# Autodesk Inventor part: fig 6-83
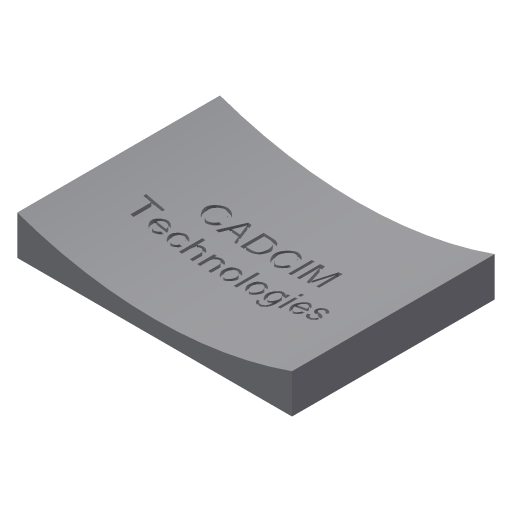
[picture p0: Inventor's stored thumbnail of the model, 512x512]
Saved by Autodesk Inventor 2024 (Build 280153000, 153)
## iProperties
Shininess: 64.0
Length Units: 11269
Angle Units: 11279
Time Units: 11290
Mass Units: 11283
Length Display Precision: 3
Angle Display Precision: 2
Compacted: True
Part Number: fig 6-83
Document SubType Name: Modeling
Created: 2002-12
Designer: deepak
Density: 1 g/cm^3
Material: Generic
Appearance: Default
Density: 0.0
Volumn: 0.0
Area: 0.0
PropertySet Name: Model Information
Control State: 0
Master: False
Checked Out: False
Author: deepak
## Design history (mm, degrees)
sketch "Sketch1"
  geometry: L1 (-39.922, 33.786)-(30.103, 33.786); L2 (30.103, 33.786)-(30.103, -17.894); L3 (30.103, -17.894)-(-39.922, -17.894); L4 (-39.922, -17.894)-(-39.922, 33.786)
  constraints: 8 end point, 2 parallel, 1 horizontal, 1 perpendicular
extrude "Extrusion1" new body sketch "Sketch1" distance "d0" = 10; taper "d1" = 0 deg
workplane "Work Plane1"
sketch "Sketch2"
  geometry: L1 (-37.656, 15.034)-(26.28, 15.034); L2 (26.28, 15.034)-(26.28, 10.168); L3 (26.28, 10.168)-(-37.656, 10.168); L4 (-37.656, 10.168)-(-37.656, 15.034)
  constraints: 2 other
sketch "Sketch3"
  geometry: L1 (70.026, 10)-(0, 10) reference; A1 r 105 centre (35.013, 108.99) between (0, 10) and (70.026, 10)
  constraints: 2 point on circle, 1 centre point
  dimensions: "d5" = 105 radius of A1
extrude "Extrusion2" cut sketch "Sketch3" extent not by distance; stored distance "d3" = 10; taper "d4" = 0 deg
emboss "Emboss4" sketch "Sketch2" dims "d14" = 1, "d15" = 0
body "Solid1"
other parameters: "d2" = 5
